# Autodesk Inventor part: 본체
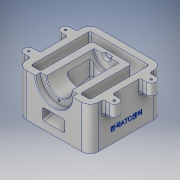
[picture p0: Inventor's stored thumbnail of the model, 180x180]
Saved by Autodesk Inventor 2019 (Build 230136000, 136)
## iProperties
Created: 2022-03
Part Number: 본체
Material: 알루미늄 6061
Document SubType Name: Modeling
Designer: LINE501-4
Density: 2.7 g/cm^3
Appearance: 알루미늄 - 평지
Mass: 1024.24 g
Surface Area: 844.702 cm^2
Volume: 379.349 cm^3
Author: LINE501-4
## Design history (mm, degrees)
sketch "스케치1"
  geometry: L1 (42, -55)-(-42, -55); L2 (-55, -42)-(-55, 42); L3 (-42, 55)-(42, 55); L4 (55, 42)-(55, -42); L5 (55, -55)-(-55, 55); L6 (-55, -55)-(55, 55); L7 (-42, -45)-(42, -45); L8 (45, -42)-(45, 42); L9 (-45, 42)-(-45, -42) reference; L10 (30, 45)-(30, -33); L11 (30, -33)-(-30, -33) reference; L12 (-30, -33)-(-30, 45) reference; L13 (42, 45)-(30, 45) reference; L14 (-30, 45)-(-42, 45) reference; A1 r 13 centre (42, -42) between (42, -55) and (55, -42); A2 r 13 centre (-42, -42) between (-55, -42) and (-42, -55); A3 r 13 centre (-42, 42) between (-42, 55) and (-55, 42); A4 r 13 centre (42, 42) between (55, 42) and (42, 55); A5 r 3 centre (42, -42) between (42, -45) and (45, -42); A6 r 3 centre (42, 42) between (45, 42) and (42, 45); A7 r 3 centre (-42, 42) between (-42, 45) and (-45, 42); A8 r 3 centre (-42, -42) between (-45, -42) and (-42, -45); 1 further point
  constraints: 28 end point, 16 point on circle, 8 centre point, 8 point on line, 8 tangent, 5 parallel, 5 perpendicular, 4 horizontal, 3 equal radius, 3 vertical, 2 midpoint, 5 other
  dimensions: "d0" = 110 distance of L5.end L6.end; "d1" = 110 distance of L6.start L5.end; "d2" = 13 radius of A1; "d3" = 10 distance between parallel lines of L1 L7; "d6" = 60 distance of L10.end L11.end
extrude "돌출1" new body sketch "스케치1" distance "d7" = 65; taper "d8" = 0 deg
sketch "스케치2"
  geometry: L1 (-55, -42)-(-55, 42) reference; L2 (-65, 21)-(-55, 21) reference; L3 (-65, 35)-(-55, 35); L4 (-65, -35)-(-55, -35) reference; L5 (-65, -21)-(-55, -21); L6 (55, -42)-(55, 42) reference; L7 (65, 21)-(55, 21) reference; L8 (65, 35)-(55, 35) reference; L9 (65, -21)-(55, -21) reference; L10 (65, -35)-(55, -35) reference; A1 r 13 centre (-42, 42) between (-42, 55) and (-55, 42) reference; A2 r 7 centre (-65, 28) between (-65, 35) and (-65, 21); A3 r 7 centre (-65, -28) between (-65, -21) and (-65, -35); A4 r 7 centre (65, -28) between (65, -35) and (65, -21); A5 r 7 centre (65, 28) between (65, 21) and (65, 35); 1 further point
  constraints: 16 end point, 8 point on circle, 8 point on line, 7 horizontal, 7 perpendicular, 4 centre point, 4 tangent, 4 other
  dimensions: "d13" = 14 diameter of A2; "d15" = 14 diameter of A3; "d18" = 14 diameter of A4; "d19" = 14 diameter of A5
extrude "돌출2" join sketch "스케치2" distance "d20" = 20; taper "d21" = 0 deg
sketch "스케치3"
  geometry: A1 r 7 centre (-65, 28) between (-65, 35) and (-65, 21) reference; A2 r 7 centre (-65, -28) between (-65, -21) and (-65, -35) reference; A3 r 7 centre (65, -28) between (65, -35) and (65, -21) reference; A4 r 7 centre (65, 28) between (65, 21) and (65, 35) reference; 5 further points
  constraints: 4 coincident
hole "구멍1" sketch "스케치3" at (-65, 28), (-65, -28), (65, -28), (65, 28) diameter "d22" = 3.242; stored, may be unused: countersink angle "d26" = 90 deg, drill point angle "d28" = 118 deg; dims "d23" = 9, "d24" = 4, "d25" = 2, "d27" = 11
sketch "스케치4"
  geometry: L1 (0, 65)-(84, 65) reference; L2 (34.5, 65)-(49.5, 65); C1 r 28 at (42, 65); C2 r 19 at (42, 65); A1 r 7.5 centre (42, 65) between (34.5, 65) and (49.5, 65); 1 further point
  constraints: 3 centre point, 2 coincident, 2 end point, 2 point on circle, 2 point on line, 1 midpoint
  dimensions: "d29" = 56 diameter of C1; "d30" = 38 diameter of C2; "d35" = 15 diameter of A1
extrude "돌출3" cut sketch "스케치4" distance "d31" = 8; taper "d32" = 0 deg
extrude "돌출4" cut sketch "스케치4" distance "d33" = 80; taper "d34" = 0 deg
extrude "돌출5" cut sketch "스케치4" distance "d36" = 84; taper "d37" = 0 deg
sketch "스케치5"
  geometry: L1 (65, -25)-(65, -29) reference; L2 (57.5, -25)-(57.5, -29) reference; L3 (57.5, -25)-(59.809, -29); L4 (57.5, -29)-(65, -29) reference; L5 (57.5, -25)-(62.119, -25); L6 (59.809, -29)-(57.5, -29); L7 (57.5, -29)-(57.5, -25); L8 (65, -25)-(65, -29); 1 further point
  constraints: 10 end point, 3 collinear, 1 equal length, 1 horizontal, 1 point on line
  dimensions: "d38" = 60 deg angle of L3 L5
revolve "회전1" sketch "스케치5" stored, may be unused: angle "d39" = 90 deg
extrude "돌출6" cut sketch "스케치4" distance "d40" = 84; taper "d41" = 0 deg
sketch "스케치7"
  geometry: L1 (42, -55)-(-42, -55) reference; L2 (0, -55)-(0, -19); L3 (0, -19)-(0, 0); L4 (-17, -19)-(17, -19); L5 (17, -19)-(17, 19); L6 (17, 19)-(-17, 19); L7 (-17, 19)-(-17, -19); L8 (-17, -19)-(17, 19); L9 (17, -19)-(-17, 19)
  constraints: 16 end point, 3 midpoint, 2 parallel, 1 collinear, 1 horizontal, 1 perpendicular, 1 vertical
  dimensions: "d44" = 36 distance of L2.start L2.end; "d45" = 19 distance of L2.end L3.end (derived); "d46" = 34 distance of L6.end L5.end; "d47" = 38 distance of L5.end L4.end
extrude "돌출7" cut sketch "스케치7" distance "d50" = 30; taper "d51" = 0 deg
sketch "스케치10"
  geometry: L1 (0, -33)-(65, -33) reference; L2 (0, -33)-(30, -33); L3 (30, -33)-(9.1, 45); L4 (31.425, -19)-(11.597, 55) reference; L5 (49.025, -19)-(29.197, 55); L6 (56.515, -19)-(35, -19) reference; L7 (56.515, -19)-(35, -19) reference; L8 (49.025, -19)-(31.425, -19); L9 (0, 55)-(65, 55) reference; L10 (0, 45)-(9.1, 45); L11 (0, 45)-(65, 45) reference; L12 (0, -33)-(0, 45) reference; L13 (0, -33)-(0, 45); 1 further point
  constraints: 14 end point, 6 point on line, 2 equal length, 1 other
  dimensions: "d59" = 30 distance of L1.start L2.end; "d60" = 75 deg angle of L3 L2; "d62" = 17 distance between parallel lines of L4 L5
extrude "돌출8" cut sketch "스케치10" stored distance "d63" = 34; taper "d64" = 0 deg
extrude "돌출9" cut sketch "스케치10" stored distance "d65" = 70; taper "d66" = 0 deg
sketch "스케치11"
  geometry: L1 (84, 65)-(0, 65) reference; 2 further points
  constraints: 1 other
hole "구멍2" sketch "스케치11" at (42, 42) diameter "d68" = 3.242; stored, may be unused: countersink angle "d72" = 90 deg, drill point angle "d74" = 118 deg; dims "d69" = 9, "d70" = 4, "d71" = 2, "d73" = 11
fillet "모깎기3" dims "d76" = 1
fillet "모깎기4" dims "d77" = 3
fillet "모깎기5" dims "d78" = 3
sketch "스케치12"
  geometry: L1 (84, 0)-(0, 0) reference; L2 (-13, 0)-(-13, 65) reference; 2 further points
  constraints: 1 other
  dimensions: "d79" = 20 distance from line of L1 point (42, 20); "d80" = 55 distance from line of L2 point (42, 20)
feature "엠보싱1" sketch "스케치12" dims "d0" = 110, "d1" = 110, "d2" = 13, "d3" = 10, "d6" = 60, "d81" = 0.5, "d82" = 0
chamfer "모따기1" distance "d83" = 1; stored, may be unused: second distance "d84" = 2, angle "d85" = 45 deg
chamfer "모따기2" distance "d86" = 1; stored, may be unused: second distance "d87" = 2, angle "d88" = 45 deg
fillet "모깎기7" dims "d90" = 3
fillet "모깎기9" dims "d92" = 3
node "솔리드1"
